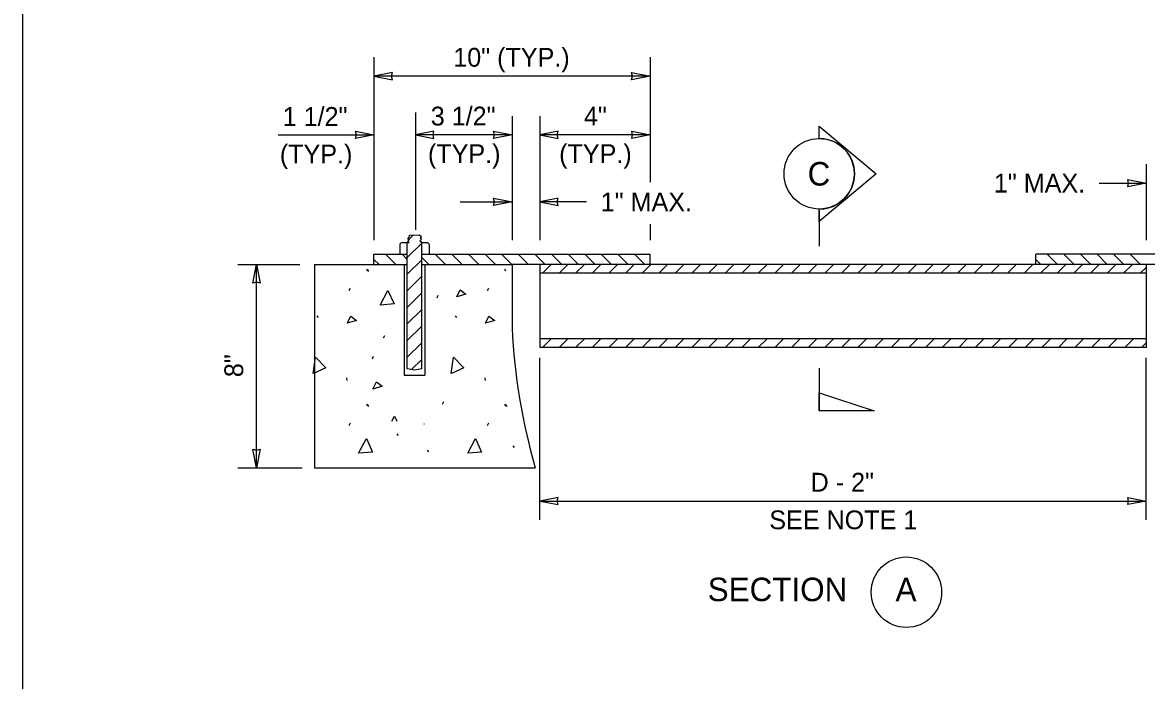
# Model space of a CAD drawing. Extents: x 99862 to 103151, y 100000 to 102076.
# Drawn here: x 99862 to 100819, y 100578 to 101138 of the extents above; entities that cross this region are included whole.
import ezdxf

# ---------------------------------------------------------------- set-up
doc = ezdxf.new("R2010")
doc.units = 0
for name, color, linetype in [('Level 1', 7, 'Continuous'), ('Level 13', 7, 'Continuous'), ('Level 15', 7, 'Continuous'), ('Level 17', 7, 'Continuous'), ('Level 18', 7, 'Continuous'), ('Level 20', 7, 'Continuous'), ('Level 9', 7, 'Continuous')]:
    doc.layers.add(name, color=color, linetype=linetype)

msp = doc.modelspace()

# ---------------------------------------------------------------- linework, layer by layer
at = {"layer": 'Level 1'}
for p, q in [((100191.7, 100955.54), (100189.77, 100953.95)), ((100189.77, 100953.95), (100191.29, 100953.18)), ((100191.29, 100953.18), (100189.77, 100951.74)), ((100189.77, 100951.74), (100191.43, 100950.63)), ((100191.7, 100956.78), (100191.01, 100956.09)), ((100191.01, 100956.09), (100191.7, 100955.54)), ((100199.87, 100956.92), (100191.7, 100956.78)), ((100201.67, 100955.54), (100199.87, 100956.92)), ((100200.42, 100952.08), (100201.95, 100953.53)), ((100202.02, 100950.83), (100200.42, 100952.08)), ((100200.56, 100954.36), (100201.67, 100955.54)), ((100201.95, 100953.53), (100200.56, 100954.36)), ((100183.54, 100940.73), (100183.54, 100949.59)), ((100185.55, 100950.7), (100191.21, 100950.7)), ((100189.7, 100843.19), (100189.7, 100950.7)), ((100201.6, 100950.56), (100202.02, 100950.83)), ((100201.84, 100950.7), (100206.44, 100950.7)), ((100201.98, 100843.19), (100201.98, 100950.7)), ((100208.65, 100940.73), (100208.65, 100948.69)), ((100161.33, 100931.95), (100161.33, 100940.73)), ((100161.33, 100940.73), (100189.7, 100940.73)), ((100187, 100931.95), (100187, 100837.8)), ((100201.98, 100940.73), (100396.56, 100940.73)), ((100204.64, 100931.95), (100204.64, 100837.8)), ((100842.52, 100931.95), (100278.93, 100931.95)), ((100302.45, 100931.95), (100302.45, 100861.38)), ((100396.56, 100931.95), (100396.56, 100940.73)), ((100724.9, 100931.95), (100724.9, 100940.73)), ((100919.48, 100940.73), (100724.9, 100940.73)), ((100818.99, 100931.95), (100818.99, 100861.38)), ((100818.99, 100924.54), (100302.45, 100924.54)), ((100818.99, 100868.71), (100302.45, 100868.71)), ((100818.99, 100861.38), (100302.45, 100861.38)), ((100187, 100837.8), (100204.64, 100837.8))]:
    msp.add_line(p, q, dxfattribs=at)
msp.add_lwpolyline([(99862, 99999.5), (103151, 99999.5), (103151, 102075.5), (99862, 102075.5)], close=True, dxfattribs=at)
msp.add_lwpolyline([(100201.98, 100843.19), (100195.84, 100842.23), (100189.7, 100843.19)], dxfattribs=at)
for centre, radius, start, end in [((100185.53, 100948.34), 2.33, 88.29585, 147.30365), ((100204.99, 100946.79), 4.13, 27.47168, 69.79443)]:
    msp.add_arc(centre, radius, start, end, dxfattribs=at)
at = {"layer": 'Level 13'}
for p, q in [((100110.72, 100931.95), (100110.72, 100759.14)), ((100110.72, 100931.95), (100189.7, 100931.95)), ((100201.98, 100931.95), (100278.94, 100931.95)), ((100278.94, 100931.95), (100278.94, 100877.93)), ((100110.72, 100759.14), (100298.56, 100759.14))]:
    msp.add_line(p, q, dxfattribs=at)
msp.add_arc((100811.96, 100904.94), 533.71, 182.90089, 195.85384, dxfattribs=at)
at = {"layer": 'Level 15'}
for p, q in [((100161.33, 101108.32), (100161.33, 100952.72)), ((100396.56, 101108.32), (100396.56, 101002.18)), ((100396.49, 101092.32), (100161.33, 101092.32)), ((100196.62, 101061.35), (100196.62, 100961.49)), ((100278.94, 101058.31), (100278.94, 100952.72)), ((100302.47, 101058.31), (100302.47, 100952.72)), ((100079.71, 101042.32), (100161.33, 101042.32)), ((100278.94, 101042.32), (100196.62, 101042.32)), ((100396.56, 101042.32), (100302.47, 101042.32)), ((100818.99, 101017.29), (100818.99, 100952.73)), ((100779, 101001.29), (100818.99, 101001.29)), ((100234.81, 100985.29), (100278.94, 100985.29)), ((100342.46, 100985.29), (100302.47, 100985.29)), ((100396.56, 100966.41), (100396.56, 100952.72)), ((100045.4, 100931.95), (100098.07, 100931.95)), ((100061.4, 100759.14), (100061.4, 100931.95)), ((100302.47, 100714.81), (100302.47, 100852.73)), ((100818.99, 100714.81), (100818.99, 100852.73)), ((100045.4, 100759.14), (100100.21, 100759.14)), ((100302.47, 100730.81), (100818.99, 100730.81))]:
    msp.add_line(p, q, dxfattribs=at)
for points in [[(100161.33, 101092.32), (100177.06, 101089.24), (100176.33, 101092.32), (100177.06, 101095.41)], [(100396.49, 101092.32), (100380.77, 101089.24), (100381.5, 101092.32), (100380.77, 101095.41)], [(100161.33, 101042.32), (100145.61, 101039.24), (100146.34, 101042.32), (100145.61, 101045.41)], [(100196.62, 101042.32), (100212.35, 101039.24), (100211.62, 101042.32), (100212.35, 101045.41)], [(100278.94, 101042.32), (100263.22, 101039.24), (100263.95, 101042.32), (100263.22, 101045.41)], [(100302.47, 101042.32), (100318.2, 101039.24), (100317.47, 101042.32), (100318.2, 101045.41)], [(100396.56, 101042.32), (100380.84, 101039.24), (100381.57, 101042.32), (100380.84, 101045.41)], [(100818.99, 101001.29), (100803.27, 100998.21), (100804, 101001.29), (100803.27, 101004.37)], [(100278.94, 100985.29), (100263.22, 100982.21), (100263.95, 100985.29), (100263.22, 100988.37)], [(100302.47, 100985.29), (100318.2, 100982.21), (100317.47, 100985.29), (100318.2, 100988.37)], [(100061.4, 100931.95), (100064.48, 100916.23), (100061.4, 100916.96), (100058.31, 100916.23)], [(100061.4, 100759.14), (100058.31, 100774.87), (100061.4, 100774.14), (100064.48, 100774.87)], [(100302.47, 100730.81), (100318.2, 100727.73), (100317.47, 100730.81), (100318.2, 100733.9)], [(100818.99, 100730.81), (100803.27, 100727.73), (100804, 100730.81), (100803.27, 100733.9)]]:
    msp.add_lwpolyline(points, close=True, dxfattribs=at)
at = {"layer": 'Level 17'}
for p, q in [((100154.83, 100928), (100155.8, 100926.55)), ((100155.8, 100927.45), (100156.76, 100926)), ((100272.51, 100928), (100273.48, 100926.55)), ((100140.3, 100909.81), (100141.27, 100912.02)), ((100215.02, 100903.65), (100215.99, 100905.86)), ((100257.98, 100909.81), (100259.02, 100912.02)), ((100112.77, 100888.43), (100113.74, 100886.98)), ((100230.52, 100888.43), (100231.48, 100886.98)), ((100169.56, 100869.54), (100170.54, 100871.76)), ((100159.95, 100851.83), (100160.92, 100854.05)), ((100138.02, 100835.57), (100138.3, 100833.36)), ((100255.77, 100835.57), (100255.98, 100833.36)), ((100154.83, 100813.23), (100155.8, 100811.77)), ((100155.8, 100812.68), (100156.76, 100811.22)), ((100219.66, 100813.23), (100220.7, 100815.44)), ((100272.51, 100813.23), (100273.48, 100811.77)), ((100273.48, 100812.68), (100274.45, 100811.22)), ((100140.3, 100795.03), (100141.27, 100797.24)), ((100204.02, 100796.14), (100204.37, 100796.9)), ((100257.98, 100795.03), (100259.02, 100797.24)), ((100180.93, 100787.96), (100181.9, 100786.51)), ((100206.76, 100774.05), (100207.73, 100772.6)), ((100279.63, 100777.69), (100280.6, 100776.24))]:
    msp.add_line(p, q, dxfattribs=at)
for points in [[(100166.59, 100897.49), (100173.23, 100910.01), (100178.42, 100898.53), (100166.87, 100897.49)], [(100231.76, 100904.48), (100234.67, 100910.57), (100239.58, 100906.9), (100231.76, 100904.48)], [(100138.57, 100882.07), (100141.54, 100888.15), (100146.46, 100884.49), (100138.57, 100882.07)], [(100256.32, 100882.07), (100259.23, 100888.15), (100264.14, 100884.49), (100256.32, 100882.07)], [(100109.51, 100839.17), (100111.45, 100853.21), (100120.24, 100844.15), (100109.72, 100839.24)], [(100227.2, 100839.17), (100229.13, 100853.21), (100237.99, 100844.15), (100227.47, 100839.24)], [(100160.43, 100826.03), (100163.41, 100832.11), (100168.32, 100828.45), (100160.43, 100826.03)], [(100176.55, 100798.7), (100178.9, 100803.13), (100180.91, 100798.7)], [(100148.27, 100771.43), (100154.91, 100783.95), (100160.03, 100772.47), (100148.48, 100771.43)], [(100241.22, 100771.43), (100247.86, 100783.95), (100252.98, 100772.47), (100241.43, 100771.43)]]:
    msp.add_lwpolyline(points, dxfattribs=at)
at = {"layer": 'Level 18'}
for p, q in [((100194.39, 100956.83), (100190.93, 100953.37)), ((100201.98, 100950.28), (100189.7, 100938)), ((100165.72, 100931.95), (100161.33, 100936.34)), ((100179.86, 100931.95), (100171.08, 100940.73)), ((100189.7, 100936.26), (100185.23, 100940.73)), ((100201.98, 100936.14), (100189.7, 100923.86)), ((100208.15, 100931.95), (100201.98, 100938.12)), ((100222.29, 100931.95), (100213.51, 100940.73)), ((100236.43, 100931.95), (100227.65, 100940.73)), ((100250.57, 100931.95), (100241.79, 100940.73)), ((100264.72, 100931.95), (100255.94, 100940.73)), ((100278.86, 100931.95), (100270.08, 100940.73)), ((100293, 100931.95), (100284.22, 100940.73)), ((100307.14, 100931.95), (100298.36, 100940.73)), ((100312.21, 100931.95), (100304.8, 100924.54)), ((100321.29, 100931.95), (100312.51, 100940.73)), ((100326.36, 100931.95), (100318.95, 100924.54)), ((100335.43, 100931.95), (100326.65, 100940.73)), ((100340.5, 100931.95), (100333.09, 100924.54)), ((100349.57, 100931.95), (100340.79, 100940.73)), ((100354.64, 100931.95), (100347.23, 100924.54)), ((100363.71, 100931.95), (100354.93, 100940.73)), ((100368.78, 100931.95), (100361.37, 100924.54)), ((100377.85, 100931.95), (100369.07, 100940.73)), ((100382.92, 100931.95), (100375.51, 100924.54)), ((100392, 100931.95), (100383.22, 100940.73)), ((100397.07, 100931.95), (100389.66, 100924.54)), ((100411.21, 100931.95), (100403.8, 100924.54)), ((100425.35, 100931.95), (100417.94, 100924.54)), ((100439.49, 100931.95), (100432.08, 100924.54)), ((100453.63, 100931.95), (100446.22, 100924.54)), ((100467.78, 100931.95), (100460.37, 100924.54)), ((100481.92, 100931.95), (100474.51, 100924.54)), ((100496.06, 100931.95), (100488.65, 100924.54)), ((100510.2, 100931.95), (100502.79, 100924.54)), ((100524.35, 100931.95), (100516.94, 100924.54)), ((100538.49, 100931.95), (100531.08, 100924.54)), ((100552.63, 100931.95), (100545.22, 100924.54)), ((100566.77, 100931.95), (100559.36, 100924.54)), ((100580.91, 100931.95), (100573.5, 100924.54)), ((100595.06, 100931.95), (100587.65, 100924.54)), ((100609.2, 100931.95), (100601.79, 100924.54)), ((100623.34, 100931.95), (100615.93, 100924.54)), ((100637.48, 100931.95), (100630.07, 100924.54)), ((100651.62, 100931.95), (100644.21, 100924.54)), ((100665.77, 100931.95), (100658.36, 100924.54)), ((100679.91, 100931.95), (100672.5, 100924.54)), ((100694.05, 100931.95), (100686.64, 100924.54)), ((100708.19, 100931.95), (100700.78, 100924.54)), ((100722.34, 100931.95), (100714.93, 100924.54)), ((100729.29, 100931.95), (100724.9, 100936.34)), ((100736.48, 100931.95), (100729.07, 100924.54)), ((100743.43, 100931.95), (100734.65, 100940.73)), ((100750.62, 100931.95), (100743.21, 100924.54)), ((100757.58, 100931.95), (100748.8, 100940.73)), ((100764.76, 100931.95), (100757.35, 100924.54)), ((100771.72, 100931.95), (100762.94, 100940.73)), ((100778.9, 100931.95), (100771.49, 100924.54)), ((100785.86, 100931.95), (100777.08, 100940.73)), ((100793.05, 100931.95), (100785.64, 100924.54)), ((100800, 100931.95), (100791.22, 100940.73)), ((100807.19, 100931.95), (100799.78, 100924.54)), ((100814.14, 100931.95), (100805.36, 100940.73)), ((100818.99, 100929.62), (100813.92, 100924.54)), ((100201.98, 100921.99), (100189.7, 100909.71)), ((100201.98, 100907.85), (100189.7, 100895.57)), ((100201.98, 100893.71), (100189.7, 100881.43)), ((100201.98, 100879.57), (100189.7, 100867.29)), ((100201.98, 100865.42), (100189.7, 100853.14)), ((100312.21, 100868.79), (100304.8, 100861.38)), ((100326.36, 100868.79), (100318.95, 100861.38)), ((100340.5, 100868.79), (100333.09, 100861.38)), ((100354.64, 100868.79), (100347.23, 100861.38)), ((100368.78, 100868.79), (100361.37, 100861.38)), ((100382.92, 100868.79), (100375.51, 100861.38)), ((100397.07, 100868.79), (100389.66, 100861.38)), ((100411.21, 100868.79), (100403.8, 100861.38)), ((100425.35, 100868.79), (100417.94, 100861.38)), ((100439.49, 100868.79), (100432.08, 100861.38)), ((100453.63, 100868.79), (100446.22, 100861.38)), ((100467.78, 100868.79), (100460.37, 100861.38)), ((100481.92, 100868.79), (100474.51, 100861.38)), ((100496.06, 100868.79), (100488.65, 100861.38)), ((100510.2, 100868.79), (100502.79, 100861.38)), ((100524.35, 100868.79), (100516.94, 100861.38)), ((100538.49, 100868.79), (100531.08, 100861.38)), ((100552.63, 100868.79), (100545.22, 100861.38)), ((100566.77, 100868.79), (100559.36, 100861.38)), ((100580.91, 100868.79), (100573.5, 100861.38)), ((100595.06, 100868.79), (100587.65, 100861.38)), ((100609.2, 100868.79), (100601.79, 100861.38)), ((100624.21, 100868.71), (100616.88, 100861.38)), ((100638.35, 100868.71), (100631.02, 100861.38)), ((100652.49, 100868.71), (100645.16, 100861.38)), ((100666.63, 100868.71), (100659.3, 100861.38)), ((100680.78, 100868.71), (100673.45, 100861.38)), ((100694.92, 100868.71), (100687.59, 100861.38)), ((100709.06, 100868.71), (100701.73, 100861.38)), ((100723.2, 100868.71), (100715.87, 100861.38)), ((100737.34, 100868.71), (100730.01, 100861.38)), ((100751.49, 100868.71), (100744.16, 100861.38)), ((100765.63, 100868.71), (100758.3, 100861.38)), ((100779.77, 100868.71), (100772.44, 100861.38)), ((100793.91, 100868.71), (100786.58, 100861.38)), ((100808.06, 100868.71), (100800.73, 100861.38)), ((100818.99, 100865.51), (100814.87, 100861.38)), ((100201.98, 100851.28), (100193.32, 100842.62))]:
    msp.add_line(p, q, dxfattribs=at)
at = {"layer": 'Level 9'}
for p, q in [((100540.53, 101039.23), (100540.53, 101049.83)), ((100540.53, 101049.83), (100588.99, 101009.23)), ((100588.99, 101009.23), (100540.53, 100968.63)), ((100540.53, 100968.63), (100540.53, 100979.23)), ((100540.53, 100977.67), (100540.53, 100947.67)), ((100540.53, 100843.95), (100540.53, 100807.42))]:
    msp.add_line(p, q, dxfattribs=at)
msp.add_lwpolyline([(100540.53, 100822.95), (100587.41, 100807.42), (100540.53, 100807.42)], close=True, dxfattribs=at)
for centre in [(100540.53, 101009.23), (100614.74, 100653.23)]:
    msp.add_circle(centre, 30, dxfattribs=at)
msp.add_arc((100540.53, 101009.23), 30, 269.99779, 90.00221, dxfattribs=at)

# ---------------------------------------------------------------- texts
at = {"layer": 'Level 20'}
for s, height, p in [('10" (TYP.)', 16, (100228.86, 101100.32)), ('1 1/2"', 16, (100083.57, 101049.98)), ('3 1/2"', 16, (100209.69, 101050.32)), ('4"', 16, (100340.15, 101050.32)), ('(TYP.)', 16, (100081.17, 101017.98)), ('(TYP.)', 16, (100207.3, 101018.32)), ('(TYP.)', 16, (100319.03, 101018.32)), ('C', 20, (100530.64, 100999.21)), ('1" MAX.', 16, (100354.46, 100977.29)), ('D - 2"', 16, (100533.19, 100738.81)), ('SEE NOTE 1', 16, (100498.01, 100706.81)), ('SECTION', 20, (100445.55, 100645.61)), ('A', 20, (100605.5, 100645.61))]:
    msp.add_text(s, height=height, dxfattribs=at).set_placement(p)
for s, rotation, p in [('1" MAX.', 360, (100689.25, 100993.29)), ('8"', 90, (100049.95, 100836.18))]:
    msp.add_text(s, height=16, rotation=rotation, dxfattribs=at).set_placement(p)

doc.saveas('drawing.dxf')
